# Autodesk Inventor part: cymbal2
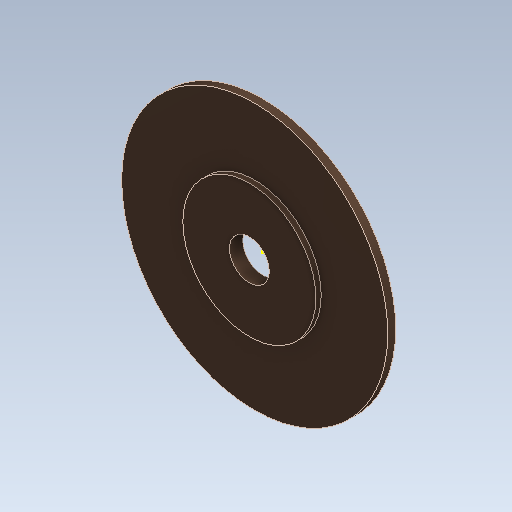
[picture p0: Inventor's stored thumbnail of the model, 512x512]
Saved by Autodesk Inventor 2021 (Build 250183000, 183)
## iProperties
Created: 2021-06
Part Number: cymbal2
Material: Bronze, Cast
Document SubType Name: Modeling
Designer: adams
Density: 8.87 g/cm^3
Appearance: Bronze - Satin
Author: adams
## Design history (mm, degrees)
sketch "Sketch1"
  geometry: 1 further point
sketch "Sketch2"
  geometry: C1 r 127 at (0, 0); 1 further point
  constraints: 1 centre point, 1 coincident
  dimensions: "d0" = 254 diameter of C1
extrude "Extrusion1" new body sketch "Sketch2" distance "d1" = 7.62; taper "d2" = 0 deg
sketch "Sketch3"
  geometry: C1 r 63.5 at (0, 0); 1 further point
  constraints: 1 centre point, 1 coincident
  dimensions: "d3" = 127 diameter of C1
extrude "Extrusion2" join sketch "Sketch3" distance "d4" = 5.08; taper "d5" = 0 deg
sketch "Sketch4"
  geometry: C1 r 19.05 at (0, 0); 1 further point
  constraints: 1 centre point, 1 coincident
  dimensions: "d6" = 38.1 diameter of C1
extrude "Extrusion3" cut sketch "Sketch4" extent not by distance; stored distance "d7" = 0; taper "d8" = 0 deg
body "Solid1"
